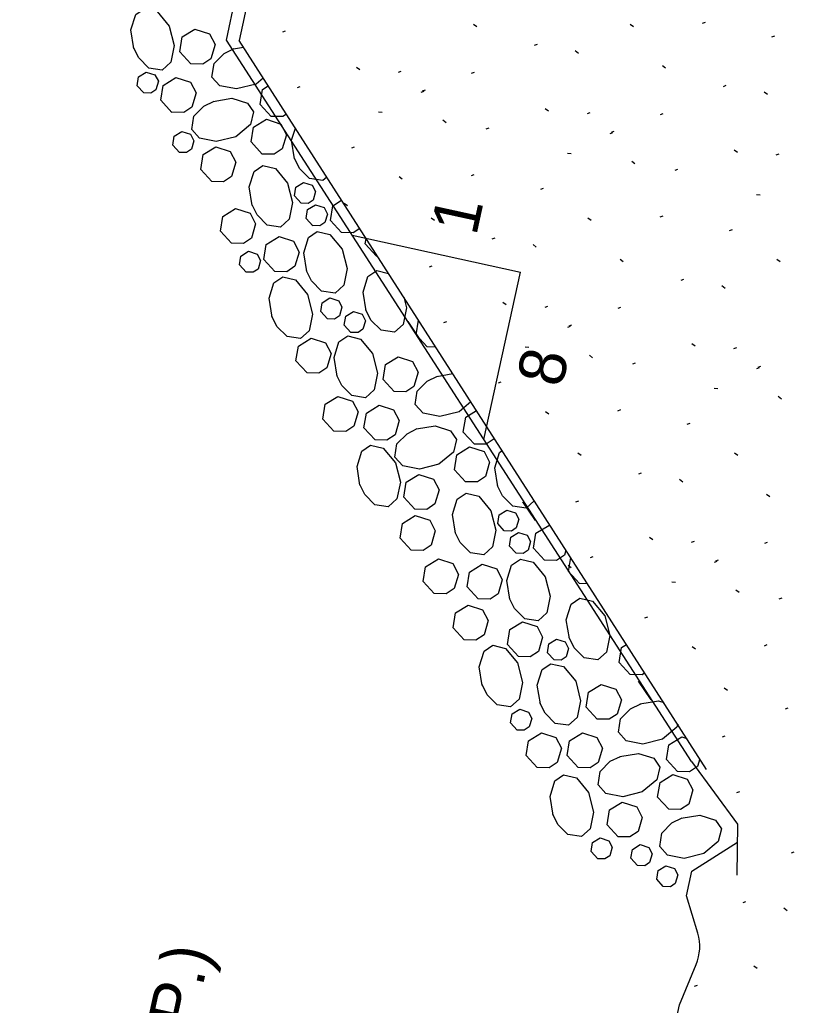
# Model space of a CAD drawing. Extents: x 2126110 to 2128246, y 1804858 to 1811658.
# Drawn here: x 2126602.6 to 2126685.7, y 1805556.7 to 1805662.4 of the extents above; entities that cross this region are included whole.
import ezdxf

# ---------------------------------------------------------------- set-up
doc = ezdxf.new("R2010")
doc.units = 0
doc.layers.add('1', color=7, linetype='Continuous')

msp = doc.modelspace()

# ---------------------------------------------------------------- linework, layer by layer
at = {"layer": '1'}
for p, q in [((2126624.81, 1805660.2), (2126630.94, 1805689.55)), ((2126632.52, 1805689.22), (2126626.17, 1805660.17)), ((2126651.67, 1805661.62), (2126651.32, 1805661.88)), ((2126668.49, 1805661.63), (2126668.14, 1805661.88)), ((2126675.89, 1805662.01), (2126676.19, 1805662.12)), ((2126674.71, 1805582.81), (2126624.81, 1805660.2)), ((2126676.32, 1805581.97), (2126626.17, 1805660.17)), ((2126630.85, 1805661.08), (2126631.15, 1805661.2)), ((2126683.33, 1805660.55), (2126683.63, 1805660.67)), ((2126625.57, 1805659.28), (2126626.63, 1805659.45)), ((2126657.87, 1805659.66), (2126658.17, 1805659.78)), ((2126662.59, 1805658.78), (2126662.24, 1805659.04)), ((2126639.11, 1805657), (2126638.76, 1805657.26)), ((2126671.93, 1805657.19), (2126671.58, 1805657.45)), ((2126643.27, 1805656.75), (2126643.57, 1805656.87)), ((2126651.12, 1805656.65), (2126651.41, 1805656.77)), ((2126632.42, 1805655.11), (2126632.72, 1805655.22)), ((2126645.86, 1805654.75), (2126646.16, 1805654.87)), ((2126678.13, 1805655.23), (2126678.43, 1805655.35)), ((2126645.72, 1805654.6), (2126646.02, 1805654.72)), ((2126682.86, 1805654.35), (2126682.5, 1805654.61)), ((2126659.37, 1805652.57), (2126659.02, 1805652.83)), ((2126641.13, 1805652.5), (2126641.53, 1805652.46)), ((2126663.53, 1805652.33), (2126663.83, 1805652.44)), ((2126671.38, 1805652.22), (2126671.68, 1805652.34)), ((2126648.38, 1805651.34), (2126648.03, 1805651.6)), ((2126652.68, 1805650.68), (2126652.98, 1805650.8)), ((2126665.99, 1805650.17), (2126666.28, 1805650.29)), ((2126666.12, 1805650.33), (2126666.42, 1805650.44)), ((2126638.27, 1805648.63), (2126638.56, 1805648.75)), ((2126661.4, 1805648.07), (2126661.8, 1805648.03)), ((2126679.64, 1805648.14), (2126679.28, 1805648.4)), ((2126683.79, 1805647.9), (2126684.09, 1805648.01)), ((2126668.64, 1805646.91), (2126668.29, 1805647.17)), ((2126643.68, 1805645.27), (2126643.33, 1805645.53)), ((2126651.09, 1805645.66), (2126651.39, 1805645.77)), ((2126672.94, 1805646.25), (2126673.24, 1805646.37)), ((2126658.53, 1805644.2), (2126658.83, 1805644.32)), ((2126681.66, 1805643.65), (2126682.06, 1805643.6)), ((2126637.79, 1805642.43), (2126637.44, 1805642.69)), ((2126671.35, 1805641.23), (2126671.65, 1805641.34)), ((2126647.13, 1805640.84), (2126646.78, 1805641.1)), ((2126663.95, 1805640.85), (2126663.6, 1805641.11)), ((2126638.31, 1805639.26), (2126656.36, 1805635.32)), ((2126678.79, 1805639.77), (2126679.09, 1805639.89)), ((2126653.33, 1805638.88), (2126653.63, 1805639)), ((2126658.05, 1805638), (2126657.7, 1805638.26)), ((2126641, 1805637.04), (2126640.9, 1805637.04)), ((2126646.58, 1805635.87), (2126646.87, 1805635.99)), ((2126667.39, 1805636.41), (2126667.04, 1805636.67)), ((2126684.21, 1805636.42), (2126683.86, 1805636.68)), ((2126652.43, 1805617.36), (2126656.36, 1805635.32)), ((2126673.59, 1805634.45), (2126673.89, 1805634.57)), ((2126678.32, 1805633.57), (2126677.96, 1805633.83)), ((2126654.83, 1805631.79), (2126654.48, 1805632.05)), ((2126658.99, 1805631.55), (2126659.29, 1805631.66)), ((2126666.84, 1805631.45), (2126667.14, 1805631.56)), ((2126644.28, 1805630), (2126645.64, 1805627.99)), ((2126648.14, 1805629.9), (2126648.44, 1805630.02)), ((2126661.45, 1805629.39), (2126661.74, 1805629.51)), ((2126661.58, 1805629.55), (2126661.88, 1805629.66)), ((2126675.1, 1805627.37), (2126674.74, 1805627.63)), ((2126647.27, 1805627.27), (2126646.34, 1805627.29)), ((2126656.86, 1805627.3), (2126657.26, 1805627.25)), ((2126664.1, 1805626.13), (2126663.75, 1805626.39)), ((2126679.25, 1805627.12), (2126679.55, 1805627.24)), ((2126668.4, 1805625.47), (2126668.7, 1805625.59)), ((2126647.37, 1805624.13), (2126649.1, 1805624.42)), ((2126681.71, 1805624.97), (2126682.01, 1805625.08)), ((2126681.84, 1805625.12), (2126682.14, 1805625.24)), ((2126653.99, 1805623.42), (2126654.29, 1805623.54)), ((2126677.12, 1805622.87), (2126677.52, 1805622.83)), ((2126684.36, 1805621.7), (2126684.01, 1805621.96)), ((2126659.41, 1805620.07), (2126659.05, 1805620.33)), ((2126666.81, 1805620.45), (2126667.11, 1805620.57)), ((2126674.25, 1805619), (2126674.55, 1805619.11)), ((2126662.85, 1805615.63), (2126662.5, 1805615.89)), ((2126679.67, 1805615.64), (2126679.32, 1805615.9)), ((2126669.05, 1805613.68), (2126669.35, 1805613.79)), ((2126673.78, 1805612.79), (2126673.42, 1805613.05)), ((2126656.57, 1805610.68), (2126657.93, 1805608.67)), ((2126662.3, 1805610.67), (2126662.6, 1805610.78)), ((2126683.11, 1805611.21), (2126682.76, 1805611.47)), ((2126670.56, 1805606.59), (2126670.2, 1805606.85)), ((2126674.71, 1805606.34), (2126675.01, 1805606.46)), ((2126682.56, 1805606.24), (2126682.86, 1805606.36)), ((2126663.86, 1805604.7), (2126664.16, 1805604.81)), ((2126677.17, 1805604.19), (2126677.47, 1805604.31)), ((2126677.3, 1805604.34), (2126677.6, 1805604.46)), ((2126661.81, 1805603.59), (2126661.46, 1805603.85)), ((2126672.58, 1805602.09), (2126672.98, 1805602.05)), ((2126663.55, 1805601.88), (2126662.7, 1805601.9)), ((2126679.82, 1805600.93), (2126679.47, 1805601.19)), ((2126684.12, 1805600.27), (2126684.42, 1805600.38)), ((2126669.71, 1805598.22), (2126670.01, 1805598.33)), ((2126675.13, 1805594.86), (2126674.78, 1805595.12)), ((2126682.54, 1805595.24), (2126682.83, 1805595.36)), ((2126668.98, 1805591.43), (2126670.34, 1805589.42)), ((2126668.98, 1805591.43), (2126670.34, 1805589.42)), ((2126678.57, 1805590.43), (2126678.22, 1805590.69)), ((2126684.77, 1805588.47), (2126685.07, 1805588.59)), ((2126678.02, 1805585.46), (2126678.32, 1805585.58)), ((2126679.58, 1805579.49), (2126679.88, 1805579.61)), ((2126685.43, 1805573.01), (2126685.73, 1805573.13)), ((2126680.23, 1805567.69), (2126680.53, 1805567.81)), ((2126684.96, 1805566.81), (2126684.6, 1805567.07)), ((2126681.74, 1805560.6), (2126681.39, 1805560.86)), ((2126675.04, 1805558.71), (2126675.34, 1805558.83))]:
    msp.add_line(p, q, dxfattribs=at)
for points in [[(2126614.89, 1805659.3), (2126614.56, 1805661.3), (2126615.08, 1805662.96), (2126616.02, 1805663.6), (2126617.39, 1805663.28), (2126618.68, 1805661.71), (2126619.21, 1805659.62), (2126618.85, 1805657.83), (2126617.92, 1805656.99), (2126616.49, 1805657.2), (2126615.4, 1805658.29), (2126614.86, 1805659.39)], [(2126621, 1805657.65), (2126619.81, 1805658.94), (2126620.07, 1805660.54), (2126621.44, 1805661.38), (2126622.99, 1805660.88), (2126623.59, 1805659.73), (2126623.14, 1805658.2), (2126622.27, 1805657.63), (2126621, 1805657.65)], [(2126628.76, 1805656.13), (2126627.99, 1805655.49), (2126625.89, 1805654.96), (2126624.11, 1805655.31), (2126623.26, 1805656.24), (2126623.48, 1805657.68), (2126624.56, 1805658.77), (2126625.66, 1805659.31)], [(2126615.95, 1805654.53), (2126615.24, 1805655.31), (2126615.39, 1805656.26), (2126616.22, 1805656.77), (2126617.15, 1805656.47), (2126617.51, 1805655.78), (2126617.24, 1805654.86), (2126616.72, 1805654.52), (2126615.95, 1805654.53)], [(2126618.96, 1805652.45), (2126617.78, 1805653.75), (2126618.03, 1805655.34), (2126619.4, 1805656.18), (2126620.96, 1805655.68), (2126621.55, 1805654.53), (2126621.1, 1805653), (2126620.23, 1805652.43), (2126618.96, 1805652.46)], [(2126629.61, 1805652.02), (2126628.42, 1805653.31), (2126628.68, 1805654.9), (2126629.3, 1805655.29)], [(2126623.4, 1805653.63), (2126625.41, 1805653.96), (2126627.07, 1805653.44), (2126627.7, 1805652.5), (2126627.38, 1805651.13), (2126625.82, 1805649.84), (2126623.72, 1805649.31), (2126621.94, 1805649.67), (2126621.09, 1805650.6), (2126621.31, 1805652.03), (2126622.39, 1805653.12), (2126623.49, 1805653.66)], [(2126628.66, 1805647.98), (2126627.48, 1805649.27), (2126627.73, 1805650.86), (2126629.1, 1805651.71), (2126630.66, 1805651.2), (2126631.25, 1805650.05), (2126630.8, 1805648.52), (2126629.93, 1805647.95), (2126628.66, 1805647.98)], [(2126631.26, 1805652.24), (2126630.88, 1805651.99), (2126629.61, 1805652.02)], [(2126632.13, 1805647.45), (2126631.81, 1805649.45), (2126632.21, 1805650.75)], [(2126619.78, 1805648.16), (2126619.07, 1805648.94), (2126619.22, 1805649.89), (2126620.04, 1805650.4), (2126620.97, 1805650.1), (2126621.33, 1805649.41), (2126621.06, 1805648.49), (2126620.54, 1805648.15), (2126619.78, 1805648.16)], [(2126623.23, 1805645.03), (2126622.05, 1805646.32), (2126622.3, 1805647.92), (2126623.67, 1805648.76), (2126625.23, 1805648.26), (2126625.82, 1805647.11), (2126625.37, 1805645.58), (2126624.5, 1805645), (2126623.23, 1805645.03)], [(2126635.57, 1805645.51), (2126635.17, 1805645.14), (2126633.73, 1805645.36), (2126632.64, 1805646.44), (2126632.1, 1805647.54)], [(2126627.59, 1805642.45), (2126627.26, 1805644.46), (2126627.78, 1805646.12), (2126628.72, 1805646.75), (2126630.09, 1805646.43), (2126631.38, 1805644.87), (2126631.91, 1805642.77), (2126631.56, 1805640.99), (2126630.63, 1805640.14), (2126629.19, 1805640.36), (2126628.1, 1805641.45), (2126627.56, 1805642.54)], [(2126632.82, 1805642.7), (2126632.11, 1805643.48), (2126632.26, 1805644.43), (2126633.08, 1805644.94), (2126634.02, 1805644.64), (2126634.37, 1805643.95), (2126634.1, 1805643.03), (2126633.58, 1805642.68), (2126632.82, 1805642.7)], [(2126634.08, 1805640.29), (2126633.37, 1805641.07), (2126633.52, 1805642.03), (2126634.35, 1805642.53), (2126635.28, 1805642.23), (2126635.64, 1805641.54), (2126635.37, 1805640.62), (2126634.85, 1805640.28), (2126634.08, 1805640.3)], [(2126637.15, 1805639.56), (2126635.96, 1805640.85), (2126636.22, 1805642.44), (2126637.16, 1805643.02)], [(2126625.35, 1805638.4), (2126624.17, 1805639.7), (2126624.42, 1805641.29), (2126625.79, 1805642.13), (2126627.35, 1805641.63), (2126627.94, 1805640.48), (2126627.49, 1805638.95), (2126626.63, 1805638.38), (2126625.35, 1805638.4)], [(2126630.02, 1805635.39), (2126628.83, 1805636.68), (2126629.09, 1805638.28), (2126630.46, 1805639.12), (2126632.01, 1805638.62), (2126632.61, 1805637.47), (2126632.16, 1805635.94), (2126631.29, 1805635.36), (2126630.02, 1805635.39)], [(2126633.43, 1805635.37), (2126633.1, 1805637.37), (2126633.61, 1805639.03), (2126634.56, 1805639.67), (2126635.92, 1805639.34), (2126637.22, 1805637.78), (2126637.75, 1805635.69), (2126637.39, 1805633.9), (2126636.46, 1805633.06), (2126635.02, 1805633.27), (2126633.93, 1805634.36), (2126633.4, 1805635.45)], [(2126639.11, 1805639.99), (2126638.42, 1805639.53), (2126637.15, 1805639.56)], [(2126640.9, 1805637.04), (2126639.71, 1805638.34), (2126639.8, 1805638.91)], [(2126626.92, 1805635.31), (2126626.2, 1805636.08), (2126626.36, 1805637.04), (2126627.18, 1805637.55), (2126628.11, 1805637.24), (2126628.47, 1805636.56), (2126628.2, 1805635.64), (2126627.68, 1805635.29), (2126626.92, 1805635.31)], [(2126629.72, 1805630.49), (2126629.39, 1805632.5), (2126629.91, 1805634.16), (2126630.85, 1805634.8), (2126632.22, 1805634.47), (2126633.51, 1805632.91), (2126634.04, 1805630.81), (2126633.68, 1805629.03), (2126632.75, 1805628.18), (2126631.32, 1805628.4), (2126630.23, 1805629.49), (2126629.69, 1805630.58)], [(2126639.8, 1805631.17), (2126639.48, 1805633.17), (2126639.99, 1805634.83), (2126640.93, 1805635.47), (2126642.2, 1805635.17)], [(2126635.66, 1805630.3), (2126634.95, 1805631.08), (2126635.1, 1805632.03), (2126635.92, 1805632.54), (2126636.86, 1805632.24), (2126637.21, 1805631.55), (2126636.94, 1805630.63), (2126636.42, 1805630.28), (2126635.66, 1805630.3)], [(2126643.84, 1805632.61), (2126644.13, 1805631.49), (2126643.77, 1805629.7), (2126642.84, 1805628.86), (2126641.4, 1805629.07), (2126640.31, 1805630.16), (2126639.77, 1805631.25)], [(2126638.17, 1805628.85), (2126637.46, 1805629.63), (2126637.61, 1805630.58), (2126638.43, 1805631.09), (2126639.36, 1805630.79), (2126639.72, 1805630.1), (2126639.45, 1805629.18), (2126638.93, 1805628.83), (2126638.17, 1805628.85)], [(2126646.34, 1805627.29), (2126645.15, 1805628.59), (2126645.41, 1805630.17)], [(2126636.69, 1805624.16), (2126636.36, 1805626.16), (2126636.87, 1805627.82), (2126637.82, 1805628.46), (2126639.18, 1805628.13), (2126640.48, 1805626.57), (2126641.01, 1805624.48), (2126640.65, 1805622.69), (2126639.72, 1805621.84), (2126638.28, 1805622.06), (2126637.19, 1805623.15), (2126636.66, 1805624.24)], [(2126633.46, 1805624.5), (2126632.27, 1805625.79), (2126632.53, 1805627.38), (2126633.9, 1805628.23), (2126635.45, 1805627.72), (2126636.05, 1805626.57), (2126635.6, 1805625.04), (2126634.73, 1805624.47), (2126633.46, 1805624.5)], [(2126642.8, 1805622.51), (2126641.61, 1805623.8), (2126641.86, 1805625.39), (2126643.24, 1805626.24), (2126644.79, 1805625.73), (2126645.39, 1805624.58), (2126644.93, 1805623.06), (2126644.07, 1805622.48), (2126642.8, 1805622.51)], [(2126651.04, 1805621.38), (2126649.78, 1805620.34), (2126647.69, 1805619.81), (2126645.91, 1805620.17), (2126645.06, 1805621.1), (2126645.27, 1805622.54), (2126646.36, 1805623.63), (2126647.46, 1805624.16)], [(2126636.34, 1805618.25), (2126635.16, 1805619.54), (2126635.41, 1805621.14), (2126636.78, 1805621.98), (2126638.34, 1805621.48), (2126638.93, 1805620.33), (2126638.48, 1805618.8), (2126637.61, 1805618.22), (2126636.34, 1805618.25)], [(2126640.76, 1805617.31), (2126639.57, 1805618.6), (2126639.83, 1805620.19), (2126641.2, 1805621.04), (2126642.75, 1805620.53), (2126643.35, 1805619.39), (2126642.9, 1805617.86), (2126642.03, 1805617.28), (2126640.76, 1805617.31)], [(2126651.41, 1805616.87), (2126650.22, 1805618.16), (2126650.48, 1805619.76), (2126651.63, 1805620.47)], [(2126645.2, 1805618.49), (2126647.2, 1805618.82), (2126648.86, 1805618.3), (2126649.5, 1805617.36), (2126649.18, 1805615.99), (2126647.61, 1805614.7), (2126645.52, 1805614.17), (2126643.74, 1805614.52), (2126642.89, 1805615.45), (2126643.1, 1805616.89), (2126644.19, 1805617.98), (2126645.29, 1805618.52)], [(2126653.56, 1805617.46), (2126653.55, 1805617.42), (2126652.68, 1805616.84), (2126651.41, 1805616.87)], [(2126639.14, 1805612.45), (2126638.82, 1805614.45), (2126639.33, 1805616.11), (2126640.27, 1805616.75), (2126641.64, 1805616.43), (2126642.94, 1805614.86), (2126643.47, 1805612.77), (2126643.11, 1805610.98), (2126642.18, 1805610.14), (2126640.74, 1805610.35), (2126639.65, 1805611.44), (2126639.11, 1805612.53)], [(2126650.46, 1805612.83), (2126649.28, 1805614.12), (2126649.53, 1805615.72), (2126650.9, 1805616.56), (2126652.46, 1805616.06), (2126653.05, 1805614.91), (2126652.6, 1805613.38), (2126651.73, 1805612.8), (2126650.46, 1805612.83)], [(2126653.93, 1805612.31), (2126653.6, 1805614.31), (2126654.12, 1805615.97), (2126654.39, 1805616.16)], [(2126645.03, 1805609.89), (2126643.85, 1805611.18), (2126644.1, 1805612.77), (2126645.47, 1805613.62), (2126647.03, 1805613.11), (2126647.62, 1805611.96), (2126647.17, 1805610.44), (2126646.3, 1805609.86), (2126645.03, 1805609.89)], [(2126649.39, 1805607.31), (2126649.06, 1805609.31), (2126649.58, 1805610.97), (2126650.52, 1805611.61), (2126651.89, 1805611.28), (2126653.18, 1805609.72), (2126653.71, 1805607.63), (2126653.36, 1805605.84), (2126652.43, 1805605), (2126650.99, 1805605.21), (2126649.9, 1805606.3), (2126649.36, 1805607.39)], [(2126657.84, 1805610.79), (2126656.97, 1805610), (2126655.53, 1805610.21), (2126654.44, 1805611.3), (2126653.9, 1805612.39)], [(2126654.62, 1805607.56), (2126653.91, 1805608.33), (2126654.06, 1805609.29), (2126654.88, 1805609.79), (2126655.81, 1805609.49), (2126656.17, 1805608.8), (2126655.9, 1805607.89), (2126655.38, 1805607.54), (2126654.62, 1805607.56)], [(2126644.63, 1805605.47), (2126643.44, 1805606.76), (2126643.7, 1805608.35), (2126645.07, 1805609.2), (2126646.62, 1805608.69), (2126647.22, 1805607.55), (2126646.77, 1805606.02), (2126645.9, 1805605.44), (2126644.63, 1805605.47)], [(2126655.88, 1805605.15), (2126655.17, 1805605.93), (2126655.32, 1805606.88), (2126656.15, 1805607.39), (2126657.08, 1805607.09), (2126657.44, 1805606.4), (2126657.17, 1805605.48), (2126656.65, 1805605.13), (2126655.88, 1805605.15)], [(2126658.95, 1805604.41), (2126657.76, 1805605.7), (2126658.02, 1805607.3), (2126659.39, 1805608.14), (2126659.57, 1805608.08)], [(2126661.24, 1805605.48), (2126661.09, 1805604.96), (2126660.22, 1805604.38), (2126658.95, 1805604.41)], [(2126647.11, 1805600.82), (2126645.92, 1805602.11), (2126646.18, 1805603.7), (2126647.55, 1805604.55), (2126649.1, 1805604.04), (2126649.7, 1805602.89), (2126649.25, 1805601.36), (2126648.38, 1805600.79), (2126647.11, 1805600.82)], [(2126655.22, 1805600.22), (2126654.9, 1805602.23), (2126655.41, 1805603.89), (2126656.35, 1805604.53), (2126657.72, 1805604.2), (2126659.02, 1805602.64), (2126659.55, 1805600.54), (2126659.19, 1805598.76), (2126658.26, 1805597.91), (2126656.82, 1805598.13), (2126655.73, 1805599.22), (2126655.19, 1805600.31)], [(2126662.7, 1805601.9), (2126661.51, 1805603.19), (2126661.75, 1805604.69)], [(2126651.82, 1805600.25), (2126650.63, 1805601.54), (2126650.88, 1805603.13), (2126652.26, 1805603.98), (2126653.81, 1805603.47), (2126654.41, 1805602.32), (2126653.95, 1805600.8), (2126653.09, 1805600.22), (2126651.82, 1805600.25)], [(2126661.6, 1805596.02), (2126661.27, 1805598.03), (2126661.79, 1805599.69), (2126662.73, 1805600.32), (2126664.1, 1805600), (2126665.39, 1805598.44), (2126665.93, 1805596.34), (2126665.57, 1805594.56), (2126664.64, 1805593.71), (2126663.2, 1805593.93), (2126662.11, 1805595.02), (2126661.57, 1805596.11)], [(2126650.31, 1805595.86), (2126649.12, 1805597.16), (2126649.38, 1805598.75), (2126650.75, 1805599.59), (2126652.3, 1805599.09), (2126652.9, 1805597.94), (2126652.45, 1805596.41), (2126651.58, 1805595.84), (2126650.31, 1805595.87)], [(2126656.14, 1805594.07), (2126654.96, 1805595.36), (2126655.21, 1805596.96), (2126656.58, 1805597.8), (2126658.14, 1805597.3), (2126658.73, 1805596.15), (2126658.28, 1805594.62), (2126657.41, 1805594.04), (2126656.14, 1805594.07)], [(2126659.97, 1805593.71), (2126659.25, 1805594.48), (2126659.41, 1805595.44), (2126660.23, 1805595.94), (2126661.16, 1805595.64), (2126661.52, 1805594.95), (2126661.25, 1805594.04), (2126660.73, 1805593.69), (2126659.97, 1805593.71)], [(2126652.26, 1805590.98), (2126651.93, 1805592.98), (2126652.45, 1805594.64), (2126653.39, 1805595.28), (2126654.76, 1805594.95), (2126656.05, 1805593.39), (2126656.58, 1805591.3), (2126656.23, 1805589.51), (2126655.3, 1805588.67), (2126653.86, 1805588.88), (2126652.77, 1805589.97), (2126652.23, 1805591.06)], [(2126668.14, 1805592.15), (2126666.95, 1805593.44), (2126667.2, 1805595.03), (2126667.73, 1805595.36)], [(2126658.49, 1805589.01), (2126658.16, 1805591.01), (2126658.67, 1805592.68), (2126659.61, 1805593.31), (2126660.98, 1805592.99), (2126662.28, 1805591.43), (2126662.81, 1805589.33), (2126662.45, 1805587.55), (2126661.52, 1805586.7), (2126660.08, 1805586.91), (2126658.99, 1805588), (2126658.45, 1805589.1)], [(2126669.69, 1805592.31), (2126669.41, 1805592.12), (2126668.14, 1805592.15)], [(2126664.59, 1805587.37), (2126663.41, 1805588.66), (2126663.66, 1805590.25), (2126665.03, 1805591.09), (2126666.59, 1805590.59), (2126667.18, 1805589.44), (2126666.73, 1805587.91), (2126665.86, 1805587.34), (2126664.59, 1805587.37)], [(2126669.17, 1805588.99), (2126671.17, 1805589.32), (2126671.72, 1805589.15)], [(2126656.01, 1805586.19), (2126655.3, 1805586.96), (2126655.45, 1805587.92), (2126656.28, 1805588.43), (2126657.21, 1805588.12), (2126657.57, 1805587.43), (2126657.3, 1805586.52), (2126656.77, 1805586.17), (2126656.01, 1805586.19)], [(2126673.22, 1805586.81), (2126673.14, 1805586.49), (2126671.58, 1805585.2), (2126669.49, 1805584.67), (2126667.7, 1805585.02), (2126666.86, 1805585.95), (2126667.07, 1805587.39), (2126668.16, 1805588.48), (2126669.25, 1805589.02)], [(2126658.16, 1805582.16), (2126656.97, 1805583.45), (2126657.23, 1805585.04), (2126658.6, 1805585.89), (2126660.16, 1805585.38), (2126660.75, 1805584.23), (2126660.3, 1805582.7), (2126659.43, 1805582.13), (2126658.16, 1805582.16)], [(2126662.56, 1805582.17), (2126661.37, 1805583.46), (2126661.63, 1805585.05), (2126663, 1805585.9), (2126664.55, 1805585.39), (2126665.15, 1805584.24), (2126664.7, 1805582.71), (2126663.83, 1805582.14), (2126662.56, 1805582.17)], [(2126673.21, 1805581.73), (2126672.02, 1805583.02), (2126672.27, 1805584.61), (2126673.65, 1805585.46), (2126674.2, 1805585.28)], [(2126667, 1805583.34), (2126669, 1805583.67), (2126670.66, 1805583.16), (2126671.3, 1805582.21), (2126670.97, 1805580.85), (2126669.41, 1805579.55), (2126667.32, 1805579.02), (2126665.53, 1805579.38), (2126664.69, 1805580.31), (2126664.9, 1805581.75), (2126665.99, 1805582.84), (2126667.08, 1805583.37)], [(2126675.59, 1805583.11), (2126675.34, 1805582.28), (2126674.48, 1805581.7), (2126673.21, 1805581.73)], [(2126674.71, 1805582.81), (2126679.64, 1805576.1), (2126679.58, 1805570.61)], [(2126659.85, 1805577.07), (2126659.53, 1805579.07), (2126660.04, 1805580.73), (2126660.98, 1805581.37), (2126662.35, 1805581.05), (2126663.65, 1805579.48), (2126664.18, 1805577.39), (2126663.82, 1805575.6), (2126662.89, 1805574.76), (2126661.45, 1805574.97), (2126660.36, 1805576.06), (2126659.82, 1805577.15)], [(2126672.26, 1805577.69), (2126671.07, 1805578.98), (2126671.33, 1805580.57), (2126672.7, 1805581.42), (2126674.25, 1805580.91), (2126674.85, 1805579.76), (2126674.4, 1805578.24), (2126673.53, 1805577.66), (2126672.26, 1805577.69)], [(2126666.83, 1805574.74), (2126665.64, 1805576.04), (2126665.9, 1805577.63), (2126667.27, 1805578.47), (2126668.83, 1805577.97), (2126669.42, 1805576.82), (2126668.97, 1805575.29), (2126668.1, 1805574.72), (2126666.83, 1805574.75)], [(2126673.61, 1805576.73), (2126675.61, 1805577.06), (2126677.27, 1805576.54), (2126677.91, 1805575.6), (2126677.58, 1805574.23), (2126676.02, 1805572.94), (2126673.93, 1805572.41), (2126672.14, 1805572.76), (2126671.3, 1805573.69), (2126671.51, 1805575.13), (2126672.6, 1805576.22), (2126673.69, 1805576.76)], [(2126664.65, 1805572.38), (2126663.94, 1805573.16), (2126664.09, 1805574.11), (2126664.92, 1805574.62), (2126665.85, 1805574.32), (2126666.21, 1805573.63), (2126665.94, 1805572.71), (2126665.42, 1805572.37), (2126664.65, 1805572.38)], [(2126668.92, 1805571.66), (2126668.21, 1805572.44), (2126668.36, 1805573.39), (2126669.19, 1805573.9), (2126670.12, 1805573.6), (2126670.48, 1805572.91), (2126670.21, 1805571.99), (2126669.68, 1805571.64), (2126668.92, 1805571.66)], [(2126675.38, 1805564.4), (2126674.17, 1805568.4), (2126674.75, 1805571.04), (2126679.62, 1805574.15)], [(2126671.68, 1805569.4), (2126670.97, 1805570.18), (2126671.12, 1805571.14), (2126671.94, 1805571.64), (2126672.88, 1805571.34), (2126673.23, 1805570.65), (2126672.96, 1805569.73), (2126672.44, 1805569.39), (2126671.68, 1805569.41)], [(2126672.43, 1805550.69), (2126672.54, 1805552.76), (2126673.4, 1805556.72), (2126675.2, 1805561.05)]]:
    msp.add_lwpolyline(points, dxfattribs=at)
msp.add_arc((2126670.59, 1805562.96), 5, 337.3624, 16.7466, dxfattribs=at)

# ---------------------------------------------------------------- texts
for s, p in [('1', (2126651.6, 1805639.1)), ('8', (2126660.79, 1805622.82)), ('6 INCHES THICK (TYP.)', (2126607.34, 1805490.34))]:
    msp.add_text(s, height=5, rotation=77.6736, dxfattribs=at).set_placement(p)

doc.saveas('drawing.dxf')
